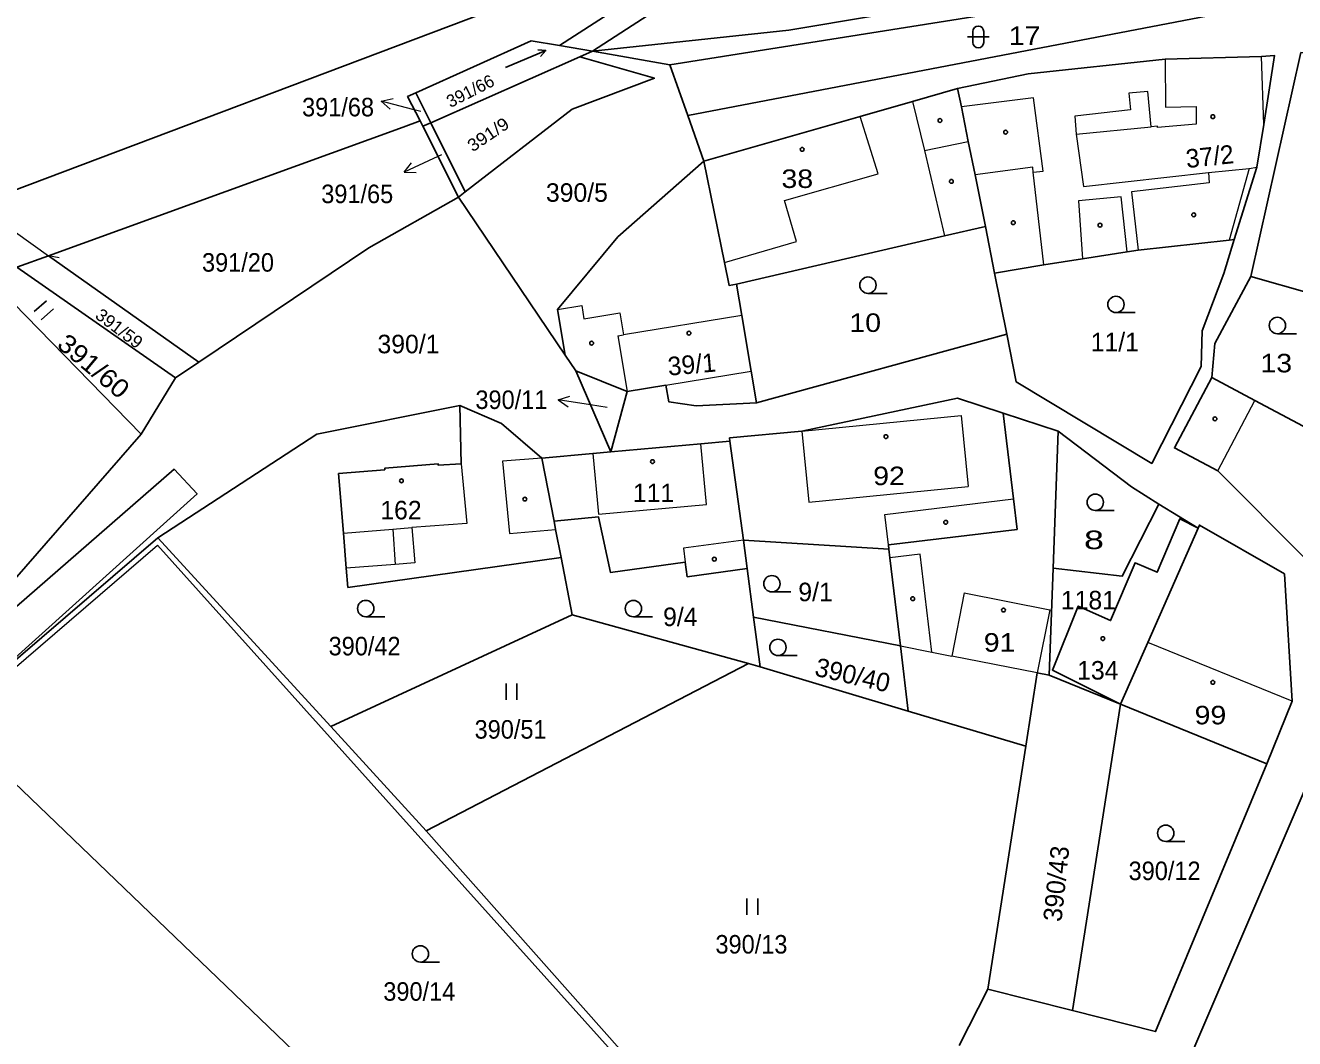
# Model space of a CAD drawing. Extents: x -758887 to -754328, y -1031688 to -1029144.
# Drawn here: x -756631.8 to -756515.3, y -1030528.5 to -1030435.5 of the extents above; entities that cross this region are included whole.
import ezdxf
from ezdxf.enums import TextEntityAlignment as Align

# ---------------------------------------------------------------- set-up
doc = ezdxf.new("R2010")
doc.units = 0
doc.header["$LTSCALE"] = 0.68
for name, color, linetype, lineweight in [('1', 7, 'Continuous', 25), ('3', 7, 'Continuous', 25), ('4', 7, 'Continuous', 13), ('5', 7, 'Continuous', 25), ('7', 7, 'Continuous', 13)]:
    doc.layers.add(name, color=color, linetype=linetype, lineweight=lineweight)
doc.layers.add('2', color=7, linetype='Continuous')

msp = doc.modelspace()

# ---------------------------------------------------------------- linework, layer by layer
at = {"layer": '1'}
for p, q in [((-756534.18, -1030408.19), (-756579.79, -1030437.87)), ((-756582.83, -1030437.35), (-756579.79, -1030437.87)), ((-756572.68, -1030439.1), (-756571.03, -1030443.77)), ((-756595.99, -1030441.68), (-756594.63, -1030444.42)), ((-756569.56, -1030447.94), (-756571.03, -1030443.77)), ((-756594.63, -1030444.42), (-756595.37, -1030444.75)), ((-756591.47, -1030450.77), (-756592.1, -1030451.26)), ((-756582.3, -1030465.75), (-756592.1, -1030451.26)), ((-756543.73, -1030453.95), (-756542.88, -1030458.24)), ((-756629.71, -1030456.63), (-756615.93, -1030466.39)), ((-756578.12, -1030474.63), (-756581.32, -1030467.2)), ((-756578.12, -1030474.63), (-756576.61, -1030469.1)), ((-756537.06, -1030472.73), (-756542.09, -1030471.08)), ((-756537.52, -1030485.31), (-756537.06, -1030472.73)), ((-756584.43, -1030475.19), (-756583.32, -1030481)), ((-756527.8, -1030479.44), (-756524.2, -1030481.63)), ((-756639, -1030499.08), (-756619.69, -1030482.51)), ((-756603.8, -1030499.82), (-756619.69, -1030482.51)), ((-756565.59, -1030485.34), (-756565.94, -1030482.72)), ((-756565.59, -1030485.34), (-756565.01, -1030489.79)), ((-756537.88, -1030495.11), (-756537.52, -1030485.31)), ((-756603.8, -1030499.82), (-756581.66, -1030489.58)), ((-756565.01, -1030489.79), (-756551.52, -1030492.43)), ((-756550.8, -1030498.41), (-756564.41, -1030494.36)), ((-756531.31, -1030497.79), (-756537.88, -1030495.11)), ((-756531.31, -1030497.79), (-756535.74, -1030525.89)), ((-756531.31, -1030497.79), (-756517.9, -1030503.26)), ((-756639, -1030499.08), (-756570.87, -1030564.48)), ((-756595.07, -1030509.4), (-756603.8, -1030499.82)), ((-756543.49, -1030523.93), (-756535.74, -1030525.89))]:
    msp.add_line(p, q, dxfattribs=at)
for points in [[(-756449.64, -1030350.85), (-756512.23, -1030391.85), (-756582.83, -1030437.35)], [(-756636.32, -1030451.94), (-756586.53, -1030433.11), (-756539.13, -1030403.35)], [(-756579.79, -1030437.87), (-756561.78, -1030435.92), (-756530.12, -1030430.62)], [(-756518.79, -1030430.39), (-756519.57, -1030430.68), (-756572.68, -1030439.1)], [(-756571.03, -1030443.77), (-756516.87, -1030433.39), (-756510.06, -1030431.65)], [(-756582.83, -1030437.35), (-756585.42, -1030436.91), (-756595.99, -1030441.68)], [(-756572.68, -1030439.1), (-756579.79, -1030437.87), (-756580.95, -1030438.38)], [(-756520.88, -1030455.14), (-756518.81, -1030448.51), (-756518.18, -1030444.6), (-756517.19, -1030438.25), (-756518.37, -1030438.35), (-756527.23, -1030438.6), (-756539.8, -1030439.93), (-756546.3, -1030441.29)], [(-756502.12, -1030440.04), (-756510.76, -1030438.1), (-756514.76, -1030437.98), (-756519.35, -1030458.53)], [(-756580.95, -1030438.38), (-756594.63, -1030444.42), (-756591.47, -1030450.77)], [(-756580.95, -1030438.38), (-756574.11, -1030440.34), (-756581.67, -1030443.19), (-756591.47, -1030450.77)], [(-756595.62, -1030444.26), (-756596.76, -1030442.02), (-756595.99, -1030441.68)], [(-756546.3, -1030441.29), (-756550.42, -1030442.47), (-756555.22, -1030443.84), (-756569.56, -1030447.94)], [(-756546.3, -1030441.29), (-756545.92, -1030442.96), (-756545.3, -1030446.14), (-756544.67, -1030449.22), (-756543.73, -1030453.95)], [(-756595.62, -1030444.26), (-756597.18, -1030444.84), (-756629.71, -1030456.63)], [(-756615.93, -1030466.39), (-756600.31, -1030455.9), (-756592.1, -1030451.26), (-756595.37, -1030444.75), (-756595.62, -1030444.26)], [(-756569.56, -1030447.94), (-756577.45, -1030454.88), (-756582.99, -1030461.56), (-756582.3, -1030465.75), (-756581.32, -1030467.2), (-756576.61, -1030469.1)], [(-756569.56, -1030447.94), (-756567.68, -1030457.25), (-756567.25, -1030459.35), (-756566.56, -1030459.24)], [(-756566.56, -1030459.24), (-756547.48, -1030454.8), (-756543.73, -1030453.95)], [(-756542.88, -1030458.24), (-756538.35, -1030457.47), (-756534.81, -1030456.92), (-756530.71, -1030456.26), (-756529.69, -1030456.13), (-756521.35, -1030455.19), (-756520.88, -1030455.14)], [(-756541.77, -1030463.84), (-756540.9, -1030468.2), (-756528.45, -1030475.68), (-756523.92, -1030466.79), (-756523.83, -1030463.52), (-756521.85, -1030458.25), (-756520.88, -1030455.14)], [(-756629.71, -1030456.63), (-756632.64, -1030457.69), (-756618.06, -1030467.83)], [(-756564.74, -1030470.12), (-756565.24, -1030467.23), (-756566.09, -1030462.1), (-756566.56, -1030459.24)], [(-756564.74, -1030470.12), (-756541.77, -1030463.84), (-756542.88, -1030458.24)], [(-756519.35, -1030458.53), (-756522.68, -1030464.69), (-756522.95, -1030467.81)], [(-756519.35, -1030458.53), (-756513.77, -1030460.12), (-756508.15, -1030461.68)], [(-756508.15, -1030461.68), (-756514.57, -1030472.26), (-756518.98, -1030469.92), (-756522.95, -1030467.81)], [(-756621.21, -1030473.01), (-756618.06, -1030467.83), (-756615.93, -1030466.39)], [(-756576.61, -1030469.1), (-756573.06, -1030468.52), (-756572.78, -1030470.04), (-756570.28, -1030470.4), (-756564.74, -1030470.12)], [(-756522.95, -1030467.81), (-756526.37, -1030474.26), (-756522.4, -1030476.37), (-756514.38, -1030484.42)], [(-756542.09, -1030471.08), (-756546.28, -1030469.71), (-756560.57, -1030472.73), (-756567.21, -1030473.35), (-756567.17, -1030473.65)], [(-756619.69, -1030482.51), (-756605.1, -1030473.01), (-756591.96, -1030470.38)], [(-756584.43, -1030475.19), (-756588.13, -1030472.01), (-756591.96, -1030470.38), (-756591.85, -1030475.73)], [(-756542.09, -1030471.08), (-756541.15, -1030478.95), (-756540.82, -1030481.74), (-756552.63, -1030483.15), (-756552.59, -1030483.55)], [(-756527.8, -1030479.44), (-756530.33, -1030477.82), (-756537.06, -1030472.73)], [(-756567.17, -1030473.65), (-756569.83, -1030473.89), (-756578.12, -1030474.63)], [(-756567.17, -1030473.65), (-756565.94, -1030482.72), (-756552.59, -1030483.55)], [(-756578.12, -1030474.63), (-756579.75, -1030474.77), (-756584.43, -1030475.19)], [(-756639, -1030499.08), (-756616.09, -1030478.48), (-756618.19, -1030476.22), (-756642.42, -1030497.3)], [(-756591.85, -1030475.73), (-756593.94, -1030475.86), (-756593.96, -1030475.72), (-756598.86, -1030476.13), (-756598.85, -1030476.27), (-756603.09, -1030476.61)], [(-756603.09, -1030476.61), (-756602.64, -1030482.09), (-756602.39, -1030485.29), (-756602.24, -1030487.07), (-756582.67, -1030484.32)], [(-756537.52, -1030485.31), (-756531.16, -1030486.02), (-756527.8, -1030479.44)], [(-756583.32, -1030481), (-756579.23, -1030480.59), (-756578.15, -1030485.68), (-756571.27, -1030484.75), (-756571.09, -1030486.09), (-756565.59, -1030485.34)], [(-756582.67, -1030484.32), (-756583.17, -1030481.76), (-756583.32, -1030481)], [(-756531.31, -1030497.79), (-756537.58, -1030494.65), (-756535.21, -1030488.78), (-756532.23, -1030490.1), (-756529.99, -1030484.8), (-756527.95, -1030485.67), (-756525.87, -1030480.76), (-756524.2, -1030481.63)], [(-756517.9, -1030503.26), (-756515.56, -1030497.49), (-756516.27, -1030485.83), (-756524.08, -1030481.35), (-756524.2, -1030481.63)], [(-756524.2, -1030481.63), (-756528.81, -1030492.11), (-756531.31, -1030497.79)], [(-756552.59, -1030483.55), (-756552.49, -1030484.34), (-756551.52, -1030492.43), (-756550.8, -1030498.41), (-756540.01, -1030501.62)], [(-756582.67, -1030484.32), (-756581.66, -1030489.58), (-756565.46, -1030494.05)], [(-756565.46, -1030494.05), (-756564.41, -1030494.36), (-756565.01, -1030489.79)], [(-756565.46, -1030494.05), (-756595.07, -1030509.4), (-756560.94, -1030547.86)], [(-756540.01, -1030501.62), (-756538.96, -1030494.9), (-756537.88, -1030495.11)], [(-756489.22, -1030526.88), (-756483.33, -1030518.31), (-756494.29, -1030510.42), (-756497.43, -1030507.94), (-756508.95, -1030497.19), (-756510.09, -1030496.54), (-756510.6, -1030496.77), (-756525.69, -1030531.93), (-756514.55, -1030537.82), (-756511.73, -1030539.11)], [(-756546.14, -1030529.11), (-756543.49, -1030523.93), (-756540.01, -1030501.62)], [(-756535.74, -1030525.89), (-756528.11, -1030527.82), (-756517.9, -1030503.26)]]:
    msp.add_lwpolyline(points, dxfattribs=at)
msp.add_lwpolyline([(-756621.21, -1030473.01), (-756634.12, -1030459.75), (-756635.21, -1030458.62), (-756661.3, -1030469.71), (-756642.42, -1030497.3)], close=True, dxfattribs=at)
at = {"layer": '3'}
for p, q in [((-756545.381, -1030436.551), (-756543.379, -1030436.551)), ((-756544.881, -1030436.051), (-756544.881, -1030437.052)), ((-756543.879, -1030437.052), (-756543.879, -1030436.051)), ((-756584.087, -1030437.795), (-756584.558, -1030438.36)), ((-756554.503, -1030460.08), (-756552.753, -1030460.08)), ((-756631.045, -1030461.744), (-756629.913, -1030460.76)), ((-756630.388, -1030462.5), (-756629.256, -1030461.516)), ((-756531.743, -1030461.85), (-756529.993, -1030461.85)), ((-756516.923, -1030463.78), (-756515.173, -1030463.78)), ((-756533.643, -1030480), (-756531.893, -1030480)), ((-756563.323, -1030487.48), (-756561.573, -1030487.48)), ((-756600.603, -1030489.75), (-756598.853, -1030489.75)), ((-756576.033, -1030489.76), (-756574.283, -1030489.76)), ((-756562.763, -1030493.32), (-756561.013, -1030493.32)), ((-756587.721, -1030497.39), (-756587.721, -1030495.89)), ((-756586.72, -1030497.39), (-756586.72, -1030495.89)), ((-756527.173, -1030510.37), (-756525.423, -1030510.37)), ((-756565.611, -1030517.11), (-756565.611, -1030515.61)), ((-756564.61, -1030517.11), (-756564.61, -1030515.61)), ((-756595.583, -1030521.44), (-756593.833, -1030521.44))]:
    msp.add_line(p, q, dxfattribs=at)
msp.add_lwpolyline([(-756587.787, -1030439.366), (-756584.087, -1030437.795), (-756584.821, -1030437.742)], dxfattribs=at)
for centre in [(-756554.5029, -1030459.3298), (-756531.7429, -1030461.0998), (-756516.9229, -1030463.0298), (-756533.6429, -1030479.2498), (-756563.3229, -1030486.7298), (-756600.6029, -1030488.9998), (-756576.0329, -1030489.0098), (-756562.7629, -1030492.5698), (-756527.1729, -1030509.6198), (-756595.5829, -1030520.6898)]:
    msp.add_circle(centre, 0.75, dxfattribs=at)
for centre, start, end in [((-756544.38, -1030436.0509), 0, 180), ((-756544.38, -1030437.0509), 180, 359.98789)]:
    msp.add_arc(centre, 0.5, start, end, dxfattribs=at)
at = {"layer": '4'}
for p, q in [((-756527.23, -1030438.6), (-756527.18, -1030442.99)), ((-756518.18, -1030444.6), (-756518.37, -1030438.35)), ((-756550.42, -1030442.47), (-756549.32, -1030446.97)), ((-756539.31, -1030442.14), (-756545.92, -1030442.96)), ((-756527.18, -1030442.99), (-756524.39, -1030442.95)), ((-756553.58, -1030449.11), (-756555.22, -1030443.84)), ((-756549.32, -1030446.97), (-756545.3, -1030446.14)), ((-756535.38, -1030445.46), (-756534.71, -1030450.29)), ((-756549.32, -1030446.97), (-756547.48, -1030454.8)), ((-756539.38, -1030448.51), (-756544.67, -1030449.22)), ((-756539.33, -1030448.96), (-756539.38, -1030448.51)), ((-756519.52, -1030448.63), (-756518.81, -1030448.51)), ((-756562.16, -1030451.55), (-756553.58, -1030449.11)), ((-756538.35, -1030457.47), (-756539.33, -1030448.96)), ((-756636.32, -1030451.94), (-756629.71, -1030456.63)), ((-756561.07, -1030455.33), (-756562.16, -1030451.55)), ((-756531.27, -1030451.23), (-756535.19, -1030451.59)), ((-756535.19, -1030451.59), (-756534.81, -1030456.92)), ((-756530.71, -1030456.26), (-756531.27, -1030451.23)), ((-756567.68, -1030457.25), (-756561.07, -1030455.33)), ((-756628.728, -1030456.821), (-756629.71, -1030456.631)), ((-756566.09, -1030462.1), (-756576.94, -1030463.88)), ((-756577.45, -1030463.97), (-756576.94, -1030463.88)), ((-756577.45, -1030463.97), (-756576.61, -1030469.1)), ((-756573.06, -1030468.52), (-756565.24, -1030467.23)), ((-756522.4, -1030476.37), (-756518.98, -1030469.92)), ((-756560.57, -1030472.73), (-756545.95, -1030471.29)), ((-756545.95, -1030471.29), (-756545.31, -1030477.81)), ((-756560.57, -1030472.73), (-756559.93, -1030479.25)), ((-756569.33, -1030479.47), (-756569.83, -1030473.89)), ((-756584.43, -1030475.19), (-756588.05, -1030475.47)), ((-756579.75, -1030474.77), (-756579.25, -1030480.35)), ((-756591.85, -1030475.73), (-756591.32, -1030481.19)), ((-756559.93, -1030479.25), (-756545.31, -1030477.81)), ((-756579.25, -1030480.35), (-756569.33, -1030479.47)), ((-756602.64, -1030482.09), (-756598.13, -1030481.71)), ((-756598.13, -1030481.71), (-756596.38, -1030481.56)), ((-756598.13, -1030481.71), (-756597.89, -1030484.96)), ((-756638.66, -1030499.45), (-756619.73, -1030483.2)), ((-756561.56, -1030547.92), (-756619.73, -1030483.2)), ((-756565.94, -1030482.72), (-756571.44, -1030483.46)), ((-756571.44, -1030483.46), (-756571.27, -1030484.75)), ((-756549.71, -1030484), (-756552.49, -1030484.34)), ((-756548.63, -1030493), (-756549.71, -1030484)), ((-756597.89, -1030484.96), (-756602.39, -1030485.29)), ((-756545.67, -1030487.57), (-756546.81, -1030493.36)), ((-756545.67, -1030487.57), (-756537.82, -1030489.11)), ((-756537.82, -1030489.11), (-756538.96, -1030494.9)), ((-756551.52, -1030492.43), (-756548.63, -1030493)), ((-756548.63, -1030493), (-756546.81, -1030493.36)), ((-756515.56, -1030497.49), (-756528.81, -1030492.11)), ((-756538.96, -1030494.9), (-756546.81, -1030493.36))]:
    msp.add_line(p, q, dxfattribs=at)
for points in [[(-756524.39, -1030442.95), (-756524.38, -1030444.55), (-756527.92, -1030444.86), (-756527.92, -1030444.75), (-756528.51, -1030444.8), (-756528.83, -1030441.55), (-756530.55, -1030441.7), (-756530.42, -1030443.24), (-756535.51, -1030443.82), (-756535.38, -1030445.46), (-756528.51, -1030444.8)], [(-756539.33, -1030448.96), (-756538.41, -1030448.86), (-756539.31, -1030442.14)], [(-756523.26, -1030448.98), (-756519.52, -1030448.63), (-756521.35, -1030455.19)], [(-756534.71, -1030450.29), (-756523.26, -1030448.98), (-756523.19, -1030449.93)], [(-756523.19, -1030449.93), (-756530.31, -1030450.75), (-756529.69, -1030456.13)], [(-756582.99, -1030461.56), (-756580.78, -1030461.19), (-756580.58, -1030462.41)], [(-756580.58, -1030462.41), (-756577.28, -1030461.86), (-756576.94, -1030463.88)], [(-756588.05, -1030475.47), (-756587.42, -1030482.11), (-756583.17, -1030481.76)], [(-756552.63, -1030483.15), (-756552.97, -1030480.37), (-756541.15, -1030478.95)], [(-756591.32, -1030481.19), (-756596.38, -1030481.56), (-756596.1, -1030484.8), (-756597.89, -1030484.96)]]:
    msp.add_lwpolyline(points, dxfattribs=at)
at = {"layer": '5'}
for centre in [(-756547.8968, -1030444.2192), (-756522.8468, -1030443.8692), (-756541.8668, -1030445.2892), (-756560.5468, -1030446.8692), (-756546.8468, -1030449.8092), (-756541.1668, -1030453.5992), (-756524.6068, -1030452.8692), (-756533.2068, -1030453.8292), (-756570.9368, -1030463.7392), (-756579.8668, -1030464.6492), (-756522.6568, -1030471.5892), (-756552.8568, -1030473.2292), (-756574.2868, -1030475.5192), (-756597.3268, -1030477.2792), (-756585.9968, -1030478.9592), (-756547.3668, -1030481.0892), (-756568.6068, -1030484.4692), (-756550.3968, -1030488.0992), (-756542.0668, -1030489.1392), (-756532.9468, -1030491.7592), (-756522.8468, -1030495.7792)]:
    msp.add_circle(centre, 0.175, dxfattribs=at)
at = {"layer": '7'}
for p, q in [((-756599.189, -1030442.433), (-756598.351, -1030443.176)), ((-756597.09, -1030448.968), (-756595.971, -1030448.999)), ((-756582.934, -1030469.841), (-756582.023, -1030470.492))]:
    msp.add_line(p, q, dxfattribs=at)
for points in [[(-756595.55, -1030443.4), (-756596.29, -1030443.21), (-756599.189, -1030442.433), (-756598.092, -1030442.209)], [(-756593.64, -1030447.36), (-756594.37, -1030447.7), (-756597.09, -1030448.968), (-756596.394, -1030448.091)], [(-756578.45, -1030470.55), (-756579.97, -1030470.31), (-756582.934, -1030469.841), (-756581.867, -1030469.503)]]:
    msp.add_lwpolyline(points, dxfattribs=at)

# ---------------------------------------------------------------- texts
at = {"layer": '2'}
for s, width, p in [('17', 1.15, (-756540.13, -1030437.29)), ('38', 1.15, (-756560.99, -1030450.41)), ('391/20', 0.95, (-756612.329, -1030458.09)), ('10', 1.15, (-756554.76, -1030463.62)), ('13', 1.15, (-756517.03, -1030467.33)), ('92', 1.15, (-756552.57, -1030477.68)), ('8', 1.45, (-756533.76, -1030483.55)), ('390/42', 0.95, (-756600.709, -1030493.3)), ('91', 1.15, (-756542.42, -1030492.96)), ('99', 1.15, (-756523.07, -1030499.63)), ('390/51', 0.95, (-756587.309, -1030500.94)), ('390/12', 0.95, (-756527.279, -1030513.92)), ('390/13', 0.95, (-756565.199, -1030520.66)), ('390/14', 0.95, (-756595.689, -1030524.99))]:
    msp.add_text(s, height=1.7, dxfattribs=dict(at, width=width)).set_placement(p, align=Align.CENTER)
for s, height, rotation, p in [('391/66', 1.14, 27, (-756590.7483, -1030442.0197)), ('37/2', 1.7, 6, (-756523.0408, -1030448.3585)), ('39/1', 1.7, 5, (-756570.6061, -1030467.4424)), ('390/40', 1.7, 347, (-756556.0937, -1030495.927)), ('390/43', 1.7, 84, (-756536.3783, -1030514.3393))]:
    msp.add_text(s, height=height, rotation=rotation, dxfattribs=at).set_placement(p, align=Align.CENTER)
at = {"layer": '2', "width": 0.95}
for s, p in [('391/68', (-756599.84, -1030443.84)), ('391/65', (-756598.08, -1030451.803)), ('390/11', (-756583.93, -1030470.69))]:
    msp.add_text(s, height=1.7, dxfattribs=at).set_placement(p, align=Align.RIGHT)
at = {"layer": '2'}
for s, height, rotation, width, p in [('391/9', 1.14, 34, 1.1, (-756589.0482, -1030445.9784)), ('391/59', 1.14, 323, 1.05, (-756623.574, -1030463.7573)), ('391/60', 1.7, 320, 1.1, (-756626.1214, -1030467.4066))]:
    msp.add_text(s, height=height, rotation=rotation, dxfattribs=dict(at, width=width)).set_placement(p, align=Align.CENTER)
for s, p in [('390/5', (-756581.22, -1030451.68)), ('390/1', (-756596.68, -1030465.58)), ('11/1', (-756531.85, -1030465.4)), ('111', (-756574.189, -1030479.24)), ('162', (-756597.369, -1030480.82)), ('9/1', (-756559.319, -1030488.33)), ('9/4', (-756571.729, -1030490.61)), ('134', (-756533.409, -1030495.52))]:
    msp.add_text(s, height=1.7, dxfattribs=at).set_placement(p, align=Align.CENTER)
msp.add_text('1181', height=1.7, dxfattribs=at).set_placement((-756536.8, -1030489.08))

doc.saveas('drawing.dxf')
